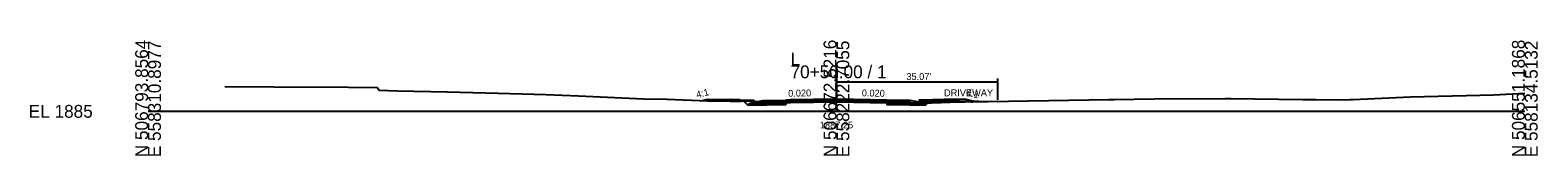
# Model space of a CAD drawing. Extents: x -26 to 4603, y -10 to 4703.
# Drawn here: x 2974.3 to 3302.8, y 200.3 to 225.5 of the extents above; entities that cross this region are included whole.
import ezdxf

# ---------------------------------------------------------------- set-up
doc = ezdxf.new("R2010")
doc.units = 0
for name, color, linetype in [('Default', 7, 'Continuous'), ('Exist Cross Section Cell', 7, 'Continuous'), ('Exist XS Ground Line', 7, 'Continuous'), ('Prop CMT Pvmt Course 1', 7, 'Continuous'), ('Prop CMT Pvmt Course 2', 7, 'Continuous'), ('Prop CMT Pvmt Course 3', 7, 'Continuous'), ('Prop CMT Pvmt Milling', 7, 'Continuous'), ('Prop CMT Shear Line', 7, 'Continuous'), ('Prop CMT Shld Paved Course 2', 7, 'Continuous'), ('Prop CMT Shld Paved Course 3', 7, 'Continuous'), ('Prop CMT Subgrade Earthwork', 7, 'Continuous'), ('Prop Conc 4in Sidewalk', 7, 'Continuous'), ('Prop Conc Curb and Gutter', 7, 'Continuous'), ('Prop Corridor Mesh Bottom', 7, 'Continuous'), ('Prop XS Finish Grade', 7, 'Continuous'), ('Prop XS Label Text', 7, 'Continuous'), ('Prop XS SS Elevation Text', 7, 'Continuous'), ('Scratch_Level_0', 7, 'Continuous'), ('Scratch_Level_9', 7, 'Continuous')]:
    doc.layers.add(name, color=color, linetype=linetype)

msp = doc.modelspace()

# ---------------------------------------------------------------- linework, layer by layer
at = {"layer": 'Exist Cross Section Cell'}
for p, q in [((3150, 210), (3150, 220)), ((3000, 210), (3150, 210)), ((3150, 210), (3300, 210))]:
    msp.add_line(p, q, dxfattribs=at)
at = {"layer": 'Exist XS Ground Line'}
msp.add_lwpolyline([(3016.73, 215.4), (3027.38, 215.33), (3043.65, 215.29), (3049.93, 215.2), (3049.99, 215.1), (3050.34, 214.6), (3054.36, 214.5), (3065.22, 214.23), (3076.27, 213.93), (3086.68, 213.67), (3093.77, 213.39), (3108.05, 212.75), (3113.13, 212.62), (3121.9, 212.31), (3124.53, 212.26), (3126.86, 212.19), (3129.27, 212.19), (3131.37, 212.25), (3131.61, 212.17), (3131.86, 212.13), (3140.01, 212.17), (3150.15, 212.25), (3163.99, 211.92), (3167.64, 211.84), (3168.01, 211.8), (3168.09, 211.8), (3168.28, 211.8), (3169.23, 211.84), (3169.39, 211.85), (3170.61, 211.88), (3170.7, 211.88), (3171.63, 211.9), (3171.71, 211.91), (3172.71, 211.93), (3172.83, 211.94), (3174.6, 211.99), (3174.71, 211.99), (3176.32, 212.04), (3176.49, 212.05), (3176.64, 212.05), (3177.81, 212.08), (3177.9, 212.09), (3178.9, 212.13), (3179.35, 212.15), (3179.38, 212.14), (3179.39, 212.07), (3179.48, 212.08), (3179.75, 212.04), (3183.05, 212.12), (3196.3, 212.34), (3209.38, 212.57), (3209.67, 212.57), (3210.5, 212.57), (3219.23, 212.74), (3234.76, 212.8), (3236.03, 212.83), (3251.57, 212.59), (3254.39, 212.56), (3259.48, 212.53), (3261.89, 212.55), (3262.06, 212.56), (3262.63, 212.56), (3275.06, 213.16), (3293.22, 213.62), (3293.25, 213.62), (3300, 213.97)], dxfattribs=at)
at = {"layer": 'Prop CMT Pvmt Course 1'}
for points in [[(3134.01, 212.36), (3139, 212.46), (3139, 212.21), (3139, 212.21), (3134.01, 212.11), (3134.01, 212.11), (3134.01, 212.11), (3134.01, 212.36), (3134.01, 212.36)], [(3140.01, 212.48), (3139, 212.46), (3139, 212.17), (3139, 212.17), (3140.01, 212.17), (3140.01, 212.17), (3150, 212.25), (3150, 212.25), (3150, 212.68), (3140.01, 212.48), (3140.01, 212.48)], [(3161, 212.46), (3150.15, 212.68), (3150.15, 212.68), (3150.15, 212.68), (3150, 212.68), (3150, 212.25), (3150, 212.25), (3150.15, 212.25), (3150.15, 212.25), (3150.15, 212.25), (3161, 212), (3161, 212), (3161, 212), (3161, 212.46), (3161, 212.46)], [(3166, 212.36), (3161, 212.46), (3161, 212.21), (3161, 212.21), (3166, 212.11), (3166, 212.11), (3166, 212.11), (3166, 212.36), (3166, 212.36)]]:
    msp.add_lwpolyline(points, dxfattribs=at)
at = {"layer": 'Prop CMT Pvmt Course 2'}
for points in [[(3134.01, 212.11), (3139, 212.21), (3139, 211.88), (3139, 211.88), (3134.01, 211.78), (3134.01, 211.78), (3134.01, 211.78), (3134.01, 212.11), (3134.01, 212.11)], [(3166, 212.11), (3161, 212.21), (3161, 211.88), (3161, 211.88), (3166, 211.78), (3166, 211.78), (3166, 211.78), (3166, 212.11), (3166, 212.11)]]:
    msp.add_lwpolyline(points, dxfattribs=at)
at = {"layer": 'Prop CMT Pvmt Course 3'}
for points in [[(3134.01, 211.78), (3139, 211.88), (3139, 211.5), (3139, 211.5), (3134.01, 211.4), (3134.01, 211.4), (3134.01, 211.4), (3134.01, 211.78), (3134.01, 211.78)], [(3166, 211.78), (3161, 211.88), (3161, 211.5), (3161, 211.5), (3166, 211.4), (3166, 211.4), (3166, 211.4), (3166, 211.78), (3166, 211.78)], [(3169, 211.72), (3166, 211.78), (3166, 211.4), (3166, 211.4), (3169.38, 211.33), (3169.38, 211.33), (3169.38, 211.33), (3169, 211.72), (3169, 211.72)]]:
    msp.add_lwpolyline(points, dxfattribs=at)
at = {"layer": 'Prop CMT Pvmt Milling'}
for points in [[(3150, 212.25), (3140.01, 212.17), (3140.01, 212.17), (3139, 212.17)], [(3161, 212), (3161, 212), (3150.15, 212.25), (3150.15, 212.25), (3150.15, 212.25), (3150, 212.25)]]:
    msp.add_lwpolyline(points, dxfattribs=at)
at = {"layer": 'Prop CMT Shld Paved Course 2'}
for points in [[(3140.01, 212.23), (3139, 212.21), (3139, 211.88), (3139, 211.88), (3140.01, 211.9), (3140.01, 211.9), (3150, 212.1), (3150, 212.1), (3150, 212.43), (3140.01, 212.23), (3140.01, 212.23)], [(3161, 212.21), (3150.15, 212.43), (3150.15, 212.43), (3150.15, 212.43), (3150, 212.43), (3150, 212.1), (3150, 212.1), (3150.15, 212.09), (3150.15, 212.09), (3150.15, 212.09), (3161, 211.88), (3161, 211.88), (3161, 211.88), (3161, 212.21), (3161, 212.21)]]:
    msp.add_lwpolyline(points, dxfattribs=at)
at = {"layer": 'Prop CMT Shld Paved Course 3'}
msp.add_lwpolyline([(3131.01, 211.72), (3134.01, 211.78), (3134.01, 211.4), (3134.01, 211.4), (3130.71, 211.34), (3130.71, 211.34), (3130.71, 211.34), (3131.01, 211.72), (3131.01, 211.72)], dxfattribs=at)
at = {"layer": 'Prop CMT Subgrade Earthwork'}
for points in [[(3129.55, 212.5), (3130.71, 211.34), (3130.71, 211.34)], [(3130.71, 211.34), (3130.71, 211.34), (3139, 211.5)], [(3169.38, 211.33), (3169.38, 211.33), (3161, 211.5)], [(3170.47, 212.42), (3169.38, 211.33), (3169.38, 211.33)]]:
    msp.add_lwpolyline(points, dxfattribs=at)
at = {"layer": 'Prop Conc 4in Sidewalk'}
msp.add_lwpolyline([(3129, 212.51), (3124, 212.61), (3123.99, 212.28), (3123.99, 212.28), (3129.01, 212.18), (3129.01, 212.18), (3129.01, 212.18), (3129, 212.51), (3129, 212.51)], dxfattribs=at)
at = {"layer": 'Prop Conc Curb and Gutter'}
for points in [[(3132.01, 211.96), (3134.01, 212.36), (3134.01, 211.78), (3134.01, 211.78), (3131.51, 211.73), (3131.51, 211.73), (3131.51, 211.73), (3131.51, 212.46), (3131.51, 212.46), (3132.01, 212.46), (3132.01, 211.96), (3132.01, 211.96), (3132.01, 211.96)], [(3168, 211.96), (3166, 212.36), (3166, 211.78), (3166, 211.78), (3168.5, 211.73), (3168.5, 211.73), (3168.5, 211.73), (3168.5, 212.46), (3168, 212.46), (3168, 212.46), (3168, 211.96), (3168, 211.96), (3168, 211.96)]]:
    msp.add_lwpolyline(points, dxfattribs=at)
at = {"layer": 'Prop Corridor Mesh Bottom'}
msp.add_lwpolyline([(3166, 212.36), (3166, 212.11)], dxfattribs=at)
at = {"layer": 'Prop XS Finish Grade'}
for p, q in [((3129, 212.51), (3131.51, 212.46)), ((3168.51, 212.46), (3185.07, 212.15))]:
    msp.add_line(p, q, dxfattribs=at)
for points in [[(3120.79, 212.35), (3120.79, 212.35), (3122.01, 212.65)], [(3122.01, 212.65), (3124, 212.61), (3124, 212.61)], [(3131.51, 212.46), (3131.5, 212.46)], [(3168.5, 212.46), (3168.51, 212.46)]]:
    msp.add_lwpolyline(points, dxfattribs=at)
at = {"layer": 'Prop XS Label Text'}
for p, q in [((3150, 217.13), (3150, 213.23)), ((3185.07, 217.13), (3185.07, 212.47)), ((3185.07, 216.33), (3150, 216.33))]:
    msp.add_line(p, q, dxfattribs=at)
at = {"layer": 'Scratch_Level_0'}
for points in [[(3168.51, 212.46), (3168.51, 212.46), (3168.5, 212.13), (3168.5, 212.13), (3168.5, 212.13), (3173.52, 212.23), (3173.52, 212.23), (3173.51, 212.56), (3168.51, 212.46)], [(3178, 212.65), (3173.51, 212.56), (3173.51, 212.56)], [(3180.38, 212.05), (3180.38, 212.05), (3178, 212.65)]]:
    msp.add_lwpolyline(points, dxfattribs=at)
at = {"layer": 'Scratch_Level_9'}
msp.add_lwpolyline([(3134.01, 212.36), (3134.01, 212.11)], dxfattribs=at)

# ---------------------------------------------------------------- texts
at = {"layer": 'Default'}
msp.add_text('-', height=0.0001, dxfattribs=at).set_placement((3000, 210))
at = {"layer": 'Exist Cross Section Cell'}
for s, p in [('N 506793.8564', (3000, 200)), ('E 558310.8977', (3002.8, 200)), ('N 506672.5216', (3150, 200)), ('E 558222.7055', (3152.8, 200)), ('N 506551.1868', (3300, 200)), ('E 558134.5132', (3302.8, 200))]:
    msp.add_text(s, height=2.8, rotation=90, dxfattribs=at).set_placement(p)
for s, p in [('70+50.00 / 1', (3140, 217.2)), ('L', (3140, 220)), ('EL 1885', (2974, 208.6))]:
    msp.add_text(s, height=2.8, dxfattribs=at).set_placement(p)
at = {"layer": 'Prop CMT Shear Line'}
for p in [(3120.79, 212.34), (3122.01, 212.65), (3126.5, 212.56), (3131.5, 212.46), (3132.01, 211.96), (3134.01, 212.36), (3134.01, 212.36), (3150, 212.68), (3166, 212.36), (3166, 212.36), (3168, 211.96), (3168.51, 212.46), (3173.51, 212.56), (3180.38, 212.05)]:
    msp.add_text('X', height=0.0025, dxfattribs=at).set_placement(p)
at = {"layer": 'Prop XS Label Text'}
for s, rotation, p in [("35.07'", 0.0969, (3165.24, 216.83)), ('4:1', 14.0362, (3119.63, 212.87)), ('0.020', 1.1458, (3139.49, 213.17)), ('0.020', 358.8542, (3155.51, 213.27)), ('DRIVEWAY', 0.0969, (3173.44, 213.28))]:
    msp.add_text(s, height=1.5, rotation=rotation, dxfattribs=at).set_placement(p)
at = {"layer": 'Prop XS SS Elevation Text'}
msp.add_text('1887.25', height=1.5, dxfattribs=at).set_placement((3146.39, 206.27))
at = {"layer": 'Scratch_Level_0'}
msp.add_text('4:1', height=1.5, rotation=345.9638, dxfattribs=at).set_placement((3178.16, 213.46))
msp.add_text('X', height=0.0025, dxfattribs=at).set_placement((3178, 212.65))

doc.saveas('drawing.dxf')
